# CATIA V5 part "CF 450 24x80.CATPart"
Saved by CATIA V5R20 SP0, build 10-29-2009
Part number: CF 450 24x80
Definition: NONE
Nomenclature: CF 450 24x80
Source: Unknown
Description: CF 450 24x80
Bounding box of the stored display mesh (mm): x -22 to 22, y 0 to 80, z -22 to 22
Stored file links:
  C:\Users\Utente\Desktop\IO LAVORO\3D X SITO CF\X SITO\CF 450\CF 450 24x80.CATPart
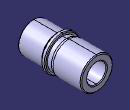
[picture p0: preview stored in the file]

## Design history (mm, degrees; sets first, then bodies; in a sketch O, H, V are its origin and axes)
Body1 "CF 450 24x80" (main body)
  Solid1: solid without history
